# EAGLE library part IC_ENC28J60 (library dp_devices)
Ethernet Controller with SPI Interface
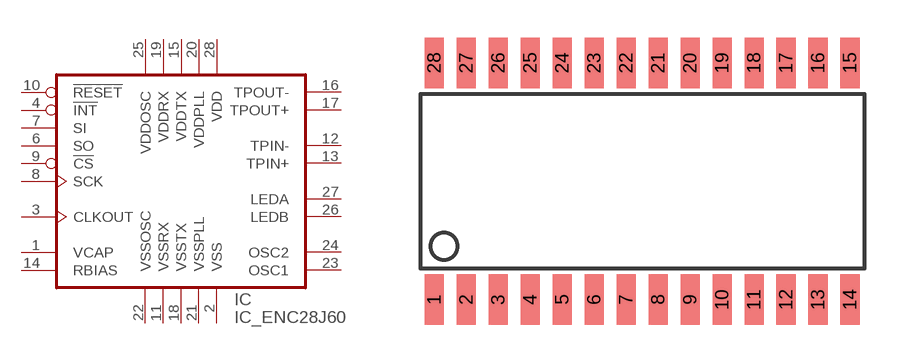
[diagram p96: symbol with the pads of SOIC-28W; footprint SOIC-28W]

Designator prefix IC

## IC_ENC28J60-SOIC-28  [SOIC-28W]
1  VCAP  in
2  VSS  sup
3  CLKOUT  out
4  !INT  out
6  SO  out
7  SI  in
8  SCK  in
9  !CS  in
10  !RESET  in
11  VSSRX  sup
12  TPIN-  in
13  TPIN+  in
14  RBIAS  in
15  VDDTX  sup
16  TPOUT-  out
17  TPOUT+  out
18  VSSTX  sup
19  VDDRX  sup
20  VDDPLL  sup
21  VSSPLL  sup
22  VSSOSC  sup
23  OSC1  in
24  OSC2  out
25  VDDOSC  sup
26  LEDB  out
27  LEDA  out
28  VDD  sup

## Footprint SOIC-28W (pad centres in mm)
smd 0.762 x 2: 1 -8.89,-4.7; 2 -7.62,-4.7; 3 -6.35,-4.7; 4 -5.08,-4.7; 5 -3.81,-4.7; 6 -2.54,-4.7; 7 -1.27,-4.7; 8 0,-4.7; 9 1.27,-4.7; 10 2.54,-4.7; 11 3.81,-4.7; 12 5.08,-4.7; 13 6.35,-4.7; 14 7.62,-4.7; 15 7.62,4.7; 16 6.35,4.7; 17 5.08,4.7; 18 3.81,4.7; 19 2.54,4.7; 20 1.27,4.7; 21 0,4.7; 22 -1.27,4.7; 23 -2.54,4.7; 24 -3.81,4.7; 25 -5.08,4.7; 26 -6.35,4.7; 27 -7.62,4.7; 28 -8.89,4.7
